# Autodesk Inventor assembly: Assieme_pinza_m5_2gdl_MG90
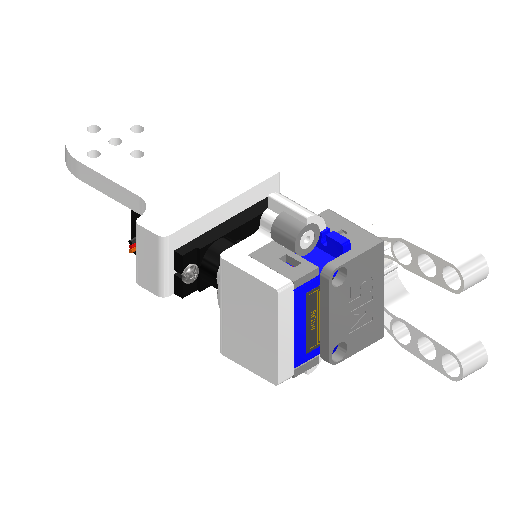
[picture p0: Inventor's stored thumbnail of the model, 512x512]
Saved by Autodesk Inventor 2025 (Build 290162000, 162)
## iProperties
Created: 2021-06
Part Number: Assieme_pinza_m5_2gdl_MG90
Document SubType Name: Assembly
Designer: Ryzen5700u
Author: Ryzen5700u
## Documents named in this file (8)
- C:\Users\Ryzen5700u\Desktop\robot nema 14\pinza\Assieme_pinza_m5_2gdl_MG90.iam
- C:\Users\Ryzen5700u\Desktop\robot nema 14\pinza\Assieme_pinza_m5.iam
- C:\Users\Ryzen5700u\Desktop\robot nema 14\pinza\MG90S_assieme_disco_ldb2.iam
- C:\Users\Ryzen5700u\Desktop\robot nema 14\pinza\corpo_MG90.ipt
- C:\Users\Ryzen5700u\Desktop\robot nema 14\pinza\disco_MG90s.ipt
- C:\Users\Ryzen5700u\Desktop\robot nema 14\pinza\link2_MG90.ipt
- C:\Users\Ryzen5700u\Desktop\robot nema 14\pinza\AS 1427 - M2,5 x 8(6) I.ipt
- C:\Users\Ryzen5700u\Desktop\robot nema 14\pinza\Screw GB_T 6561 M2 x 6.ipt
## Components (11 placed, 7 different names)
1. Assieme_pinza_m5:1 [sub-assembly]
2. MG90S_assieme_disco_ldb2:1 [sub-assembly]
3. corpo_MG90:1
4. disco_MG90s:1
5. link2_MG90:1
6. AS 1427 Z - Metrico M2,5 x 8:1
7. AS 1427 Z - Metrico M2,5 x 8:2
8. Tapping screw GB/T 6561 M2x6:1
9. Tapping screw GB/T 6561 M2x6:2
10. Tapping screw GB/T 6561 M2x6:3
11. Tapping screw GB/T 6561 M2x6:4
